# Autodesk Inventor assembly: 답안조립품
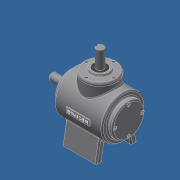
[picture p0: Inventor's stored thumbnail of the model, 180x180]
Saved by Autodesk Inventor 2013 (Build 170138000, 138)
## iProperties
Created: 2015-01
Part Number: 답안조립품
Document SubType Name: Assembly
Designer: kb146
Author: kb146
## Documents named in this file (15)
- C:\Users\kb146\Desktop\450105V1034\답안조립품.iam
- C:\Users\kb146\Desktop\450105V1034\본체.ipt
- C:\Users\kb146\Desktop\450105V1034\메인 축.ipt
- 메인 축.ipt
- C:\Users\kb146\Desktop\450105V1034\키 5x5.ipt
- C:\Users\kb146\Desktop\450105V1034\서브 축.ipt
- 서브 축.ipt
- C:\Users\kb146\Desktop\450105V1034\키 4x4.ipt
- C:\Users\kb146\Desktop\450105V1034\메인 베벨기어.ipt
- C:\Users\kb146\Desktop\450105V1034\서브 베벨기어.ipt
- C:\Users\kb146\Desktop\450105V1034\베어링 6203.ipt
- C:\Users\kb146\Desktop\450105V1034\커버.ipt
- C:\Users\kb146\Desktop\450105V1034\오일실.ipt
- C:\Users\kb146\Desktop\450105V1034\커버2.ipt
- C:\Users\kb146\Desktop\450105V1034\M4.ipt
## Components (12 placed, 1 different names)
1. M4:3
2. M4:4
3. M4:5
4. M4:6
5. M4:1
6. M4:7
7. M4:8
8. M4:9
9. M4:2
10. M4:10
11. M4:11
12. M4:12
